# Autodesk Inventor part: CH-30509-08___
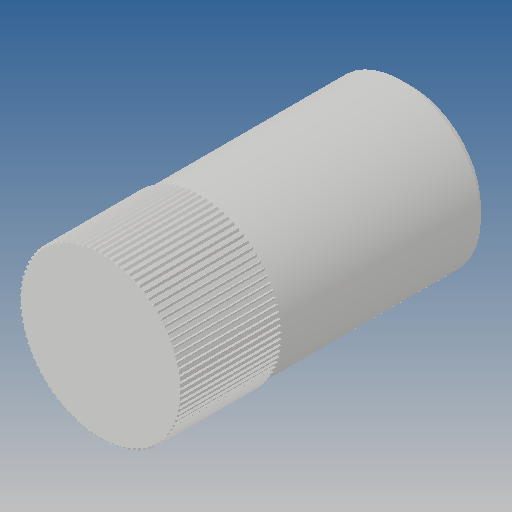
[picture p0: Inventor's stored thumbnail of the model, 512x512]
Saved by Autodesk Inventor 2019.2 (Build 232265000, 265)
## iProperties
Created: 2010-06
Part Number: CH-30509-08___
Material: Ogólny
Document SubType Name: Modeling
Designer: CADENGINEERING4
Density: 1 g/cm^3
Appearance: Domyślna
Author: CADENGINEERING4
Revision Number: ANY
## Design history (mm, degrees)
feature "NONE"
node "Bryła1"
